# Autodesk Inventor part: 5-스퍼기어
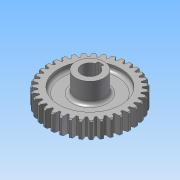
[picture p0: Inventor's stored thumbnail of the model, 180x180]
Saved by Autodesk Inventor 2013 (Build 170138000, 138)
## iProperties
Created: 2013-08
Part Number: 5-스퍼기어
Material: 강
Document SubType Name: Modeling
Designer: 한국산업디자인학원
Categories: <?xml version="1.0" encoding="UTF-16"?> <MemberInstance><Categories><FamilyTemplate><FamilyTemplateParameter ValueType="xs:double" Id="1" ObjectReferenceKey="da
Density: 1 g/cm^3
CustomPartVersion: 1
Author: 한국산업디자인학원
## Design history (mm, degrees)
sketch "Sketch1"
  geometry: C1 r 37 at (0, 0)
  constraints: 1 centre point
  dimensions: "d0" = 74 diameter of C1 (= da_da)
extrude "Extrusion1" new body sketch "Sketch1" distance "d1" = 15 (= da_b); taper "d2" = 0 deg
chamfer "모따기1" distance "d49" = 1; stored, may be unused: second distance "d50" = 2, angle "d51" = 45 deg
workplane "Work Plane2"
feature "피치 지름" dims "d4" = 10, "d5" = 0
workplane "Work Plane8"
workplane "Work Plane9"
feature "스퍼 기어" dims "da_b" = 15, "da_d" = 70, "da_aw" = 70, "da_da" = 74, "da_df" = 65, "da_dw" = 70, angle "da_beta" = 0 deg, "da_lefttooth" = 0, "da_righttooth" = 0
sketch "스케치3"
  geometry: C1 r 12.5 at (0, 0); A1 r 36 centre (0, 0) between (-5.215, 35.62) and (-7.633, 35.181) reference
  constraints: 1 centre point, 1 coincident
  dimensions: "d52" = 25 diameter of C1
extrude "돌출2" join sketch "스케치3" distance "d54" = 13; taper "d55" = 0 deg
sketch "스케치4"
  geometry: L1 (-2.5, 7.071)-(-2.5, 9.8); L2 (-2.5, 9.8)-(2.5, 9.8); L3 (2.5, 9.8)-(2.5, 7.071); C1 r 12.5 at (0, 0) reference; A1 r 7.5 centre (0, 0) between (-2.5, 7.071) and (2.5, 7.071)
  constraints: 6 end point, 2 parallel, 2 point on circle, 1 centre point, 1 coincident, 1 perpendicular, 1 vertical
  dimensions: "d56" = 15 diameter of A1; "d58" = 5 distance of L1.end L2.end; "d59" = 17.3 dimension on A1 L2
sketch "스케치5"
  geometry: C1 r 12.5 at (0, 0) reference
extrude "돌출3" join sketch "스케치5" distance "d60" = 3; taper "d61" = 0 deg
extrude "돌출4" cut sketch "스케치4" stored distance "d62" = 3; taper "d63" = 0 deg
sketch "스케치6"
  geometry: C1 r 12.5 at (0, 0) reference; C2 r 27.5 at (0, 0); A1 r 36 centre (0, 0) between (-5.215, 35.62) and (-7.633, 35.181) reference
  constraints: 1 centre point, 1 coincident
  dimensions: "d64" = 55 diameter of C2
extrude "돌출5" cut sketch "스케치6" distance "d66" = 5; taper "d67" = 0 deg
sketch "스케치7"
  geometry: C1 r 12.5 at (0, 0) reference; C2 r 27.5 at (0, 0); A1 r 32.5 centre (0, 0) between (9.347, 31.127) and (7.941, 31.515) reference
  constraints: 1 centre point, 1 coincident
  dimensions: "d68" = 55 diameter of C2
extrude "돌출6" cut sketch "스케치7" distance "d70" = 5; taper "d71" = 0 deg
fillet "모깎기1" dims "d72" = 3
body "Solid1"
sketch "Sketch2"
  geometry: C1 r 37 at (0, 0) reference; C2 r 35 at (0, 0)
  constraints: 1 centre point, 1 coincident
  dimensions: "d3" = 70 diameter of C2 (= da_dw)
body "Srf1"
other parameters: "d17" = 0, "d34" = 0.8976 (computed from da_z), "d39" = 0, "d41" = 0, "d47" = 0, "d48" = 0
